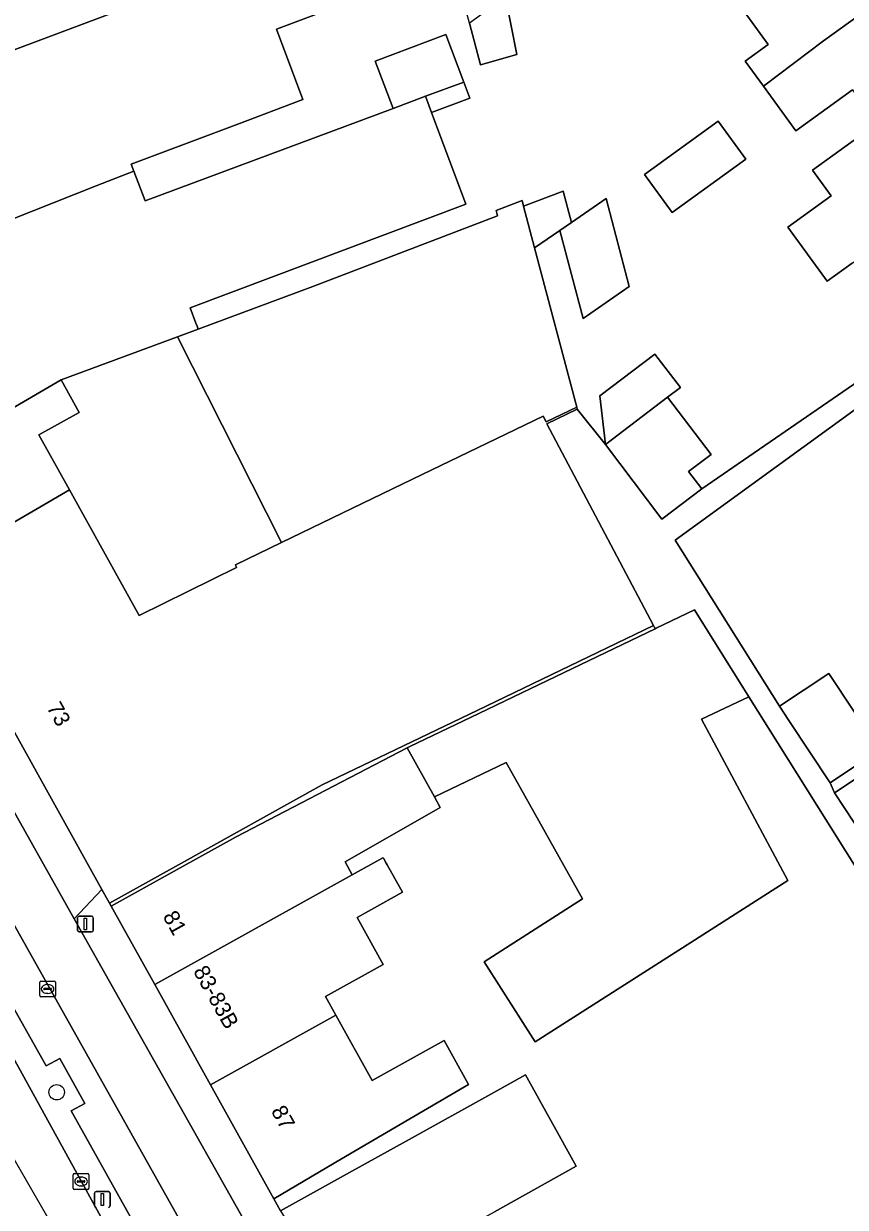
# Model space of a CAD drawing. Extents: x 161881 to 162523, y 381678 to 382381.
# Drawn here: x 162099.1 to 162151.2, y 381909.3 to 381984.4 of the extents above; entities that cross this region are included whole.
import ezdxf

# ---------------------------------------------------------------- set-up
doc = ezdxf.new("R2010")
doc.units = 0
for name, color, linetype in [('IMGEO_Berm_groen', 7, 'Continuous'), ('IMGEO_Boom', 7, 'Continuous'), ('IMGEO_Erf', 7, 'Continuous'), ('IMGEO_Fietspad_open', 7, 'Continuous'), ('IMGEO_Kolk', 7, 'Continuous'), ('IMGEO_Lichtmast', 7, 'Continuous'), ('IMGEO_Pand', 7, 'Continuous'), ('IMGEO_Pand_nummerreeks', 7, 'Continuous'), ('IMGEO_Parkeervlak_open', 7, 'Continuous'), ('IMGEO_Rijbaan_lokaal_gesloten', 7, 'Continuous'), ('IMGEO_Voetpad_open', 7, 'Continuous')]:
    doc.layers.add(name, color=color, linetype=linetype)

msp = doc.modelspace()

# ---------------------------------------------------------------- linework, layer by layer
at = {"layer": 'IMGEO_Berm_groen'}
msp.add_lwpolyline([(162071.636, 381967.886), (162076.565, 381958.577), (162107.811, 381901.826), (162108.729, 381902.414), (162110.128, 381903.311), (162108.772, 381905.652), (162107.884, 381905.166), (162102.118, 381915.454), (162102.985, 381915.921), (162101.417, 381918.762), (162100.535, 381918.293), (162094.757, 381928.54)], dxfattribs=at)
at = {"layer": 'IMGEO_Boom'}
msp.add_circle((162101.21, 381916.628), 0.489, dxfattribs=at)
at = {"layer": 'IMGEO_Erf'}
for points in [[(162088.878, 381991.295), (162094.493, 381981.199), (162124.179, 381992.364)], [(162125.323, 381987.847), (162115.138, 381984.016), (162116.818, 381979.55), (162112.686, 381977.996), (162105.938, 381975.458), (162106.111, 381975.02), (162106.819, 381973.14), (162122.531, 381978.989), (162121.401, 381981.991), (162125.885, 381983.677), (162127.02, 381980.66), (162127.406, 381979.635), (162124.971, 381978.729), (162127.156, 381972.918), (162109.673, 381966.342), (162110.039, 381965.369), (162110.109, 381965.182), (162110.177, 381965.001), (162117.448, 381967.695), (162129.146, 381972.188), (162129.064, 381972.524), (162130.709, 381973.143), (162130.801, 381972.795), (162133.313, 381973.74), (162133.841, 381971.754), (162136.036, 381973.274), (162137.511, 381967.703), (162134.579, 381965.674), (162133.103, 381971.247), (162131.502, 381970.146), (162134.174, 381960.054), (162134.209, 381959.922), (162135.993, 381957.684), (162135.646, 381960.777), (162139.13, 381963.42), (162140.746, 381961.291), (162139.941, 381960.68), (162142.691, 381957.057), (162141.26, 381955.971), (162142.099, 381954.866), (162155.378, 381964.012)], [(162151.659, 381980.171), (162148.072, 381977.568), (162146.018, 381980.399), (162144.863, 381981.99), (162146.312, 381983.042), (162143.669, 381986.685)], [(162151.63, 381969.178), (162150.052, 381968.034), (162147.56, 381971.47), (162150.299, 381973.457), (162149.133, 381975.065), (162153.215, 381978.026)], [(162161.41, 381966.864), (162140.416, 381951.63), (162147.039, 381941.108), (162150.163, 381943.18), (162153.377, 381938.326), (162150.238, 381936.248), (162150.507, 381935.6), (162155.548, 381938.937)], [(162158.021, 381921.094), (162145.094, 381941.696), (162142.094, 381940.269), (162147.556, 381930.049), (162140.649, 381925.635), (162131.552, 381919.822), (162128.311, 381924.893), (162134.552, 381928.882), (162129.711, 381937.528), (162125.164, 381935.343), (162125.512, 381934.681), (162119.488, 381931.238), (162119.947, 381930.412), (162121.875, 381931.484), (162121.933, 381931.457), (162122.106, 381931.146), (162122.158, 381931.053), (162123.131, 381929.304), (162121.17, 381928.214), (162120.249, 381927.702), (162121.906, 381924.722), (162118.249, 381922.689), (162118.9, 381921.518), (162121.208, 381917.368), (162125.767, 381919.903), (162127.316, 381917.118), (162119.275, 381912.403), (162114.979, 381909.883), (162115.406, 381909.104), (162119.776, 381911.535), (162123.36, 381913.529), (162128.916, 381916.62), (162130.922, 381917.736), (162134.148, 381911.935), (162128.959, 381909.049)]]:
    msp.add_lwpolyline(points, dxfattribs=at)
for points in [[(162126.111, 381989.03), (162128.955, 381989.793), (162129.671, 381986.056), (162130.37, 381982.407), (162128.086, 381981.748), (162127.369, 381984.391)], [(162138.482, 381974.79), (162143.141, 381978.171), (162144.891, 381975.762), (162140.231, 381972.381)], [(162108.867, 381964.516), (162101.493, 381961.784), (162102.644, 381959.714), (162100.084, 381958.29), (162102.018, 381954.814), (162106.444, 381946.857), (162112.612, 381949.9), (162112.537, 381950.052), (162115.472, 381951.478)], [(162139.141, 381946.01), (162139.038, 381946.204), (162127.861, 381940.832), (162118.036, 381936.109), (162108.932, 381931.046), (162104.562, 381928.615), (162104.671, 381928.417), (162109.041, 381930.848), (162112.594, 381932.824), (162123.423, 381938.453), (162123.598, 381938.538), (162127.969, 381940.639), (162131.792, 381942.477)]]:
    msp.add_lwpolyline(points, close=True, dxfattribs=at)
at = {"layer": 'IMGEO_Fietspad_open'}
for points in [[(162117.066, 381901.457), (162102.32, 381927.62), (162087.64, 381953.76), (162075.194, 381976.109)], [(162076.214, 381967.086), (162084.266, 381952.579), (162111.528, 381904.042)]]:
    msp.add_lwpolyline(points, dxfattribs=at)
at = {"layer": 'IMGEO_Kolk'}
for p, q in [((162100.134, 381922.752), (162100.134, 381923.604)), ((162100.209, 381923.678), (162101.061, 381923.678)), ((162100.393, 381923.172), (162100.393, 381923.184)), ((162100.831, 381923.135), (162100.433, 381923.135)), ((162100.436, 381923.221), (162100.834, 381923.221)), ((162100.622, 381923.458), (162100.647, 381923.458)), ((162100.877, 381923.184), (162100.877, 381923.172)), ((162101.135, 381923.604), (162101.135, 381922.752)), ((162101.061, 381922.678), (162100.209, 381922.678)), ((162100.645, 381922.898), (162100.62, 381922.898)), ((162102.256, 381910.547), (162102.256, 381911.399)), ((162102.331, 381911.473), (162103.183, 381911.473)), ((162102.744, 381911.253), (162102.769, 381911.253)), ((162103.257, 381911.399), (162103.257, 381910.547)), ((162103.183, 381910.473), (162102.331, 381910.473)), ((162102.515, 381910.967), (162102.515, 381910.979)), ((162102.953, 381910.93), (162102.555, 381910.93)), ((162102.558, 381911.016), (162102.956, 381911.016)), ((162102.767, 381910.693), (162102.742, 381910.693)), ((162102.999, 381910.979), (162102.999, 381910.967))]:
    msp.add_line(p, q, dxfattribs=at)
for points in [[(162100.134, 381922.752), (162100.134, 381923.604)], [(162100.209, 381923.678), (162101.061, 381923.678)], [(162101.135, 381923.604), (162101.135, 381922.752)], [(162101.061, 381922.678), (162100.209, 381922.678)], [(162102.256, 381910.547), (162102.256, 381911.399)], [(162102.331, 381911.473), (162103.183, 381911.473)], [(162103.257, 381911.399), (162103.257, 381910.547)], [(162103.183, 381910.473), (162102.331, 381910.473)]]:
    msp.add_lwpolyline(points, dxfattribs=at)
for centre, radius, start, end in [((162100.211, 381923.602), 0.0765, 91.55205, 178.44795), ((162100.211, 381923.602), 0.0765, 91.55205, 178.44795), ((162100.433, 381923.181), 0.0403, 85.87752, 175.75265), ((162100.43, 381923.171), 0.0366, 178.93798, 274.71019), ((162100.834, 381923.178), 0.043, 264.86636, 352.45326), ((162100.838, 381923.183), 0.0386, 1.73085, 96.63898), ((162101.059, 381923.602), 0.0765, 1.55205, 88.44795), ((162101.059, 381923.602), 0.0765, 1.55205, 88.44795), ((162100.211, 381922.754), 0.0765, 181.55205, 268.44795), ((162100.211, 381922.754), 0.0765, 181.55205, 268.44795), ((162101.059, 381922.754), 0.0765, 271.55205, 358.44795), ((162101.059, 381922.754), 0.0765, 271.55205, 358.44795), ((162102.333, 381911.397), 0.0765, 91.55205, 178.44795), ((162102.333, 381911.397), 0.0765, 91.55205, 178.44795), ((162103.181, 381911.397), 0.0765, 1.55205, 88.44795), ((162103.181, 381911.397), 0.0765, 1.55205, 88.44795), ((162102.333, 381910.549), 0.0765, 181.55205, 268.44795), ((162102.333, 381910.549), 0.0765, 181.55205, 268.44795), ((162102.555, 381910.976), 0.0403, 85.87752, 175.75265), ((162102.552, 381910.966), 0.0366, 178.93798, 274.71019), ((162102.956, 381910.973), 0.043, 264.86636, 352.45326), ((162102.96, 381910.978), 0.0386, 1.73085, 96.63898), ((162103.181, 381910.549), 0.0765, 271.55205, 358.44795), ((162103.181, 381910.549), 0.0765, 271.55205, 358.44795)]:
    msp.add_arc(centre, radius, start, end, dxfattribs=at)
for centre, major_axis, ratio, start_param, end_param in [((162100.621, 381923.178), (-0.387, 0.002), 0.722429, 4.712389, 7.853982), ((162100.646, 381923.178), (-0.39, 0.002), 0.717154, 1.570796, 4.712389), ((162102.743, 381910.973), (-0.387, 0.002), 0.722429, 4.712389, 7.853982), ((162102.768, 381910.973), (-0.39, 0.002), 0.717154, 1.570796, 4.712389)]:
    msp.add_ellipse(centre, major_axis=major_axis, ratio=ratio, start_param=start_param, end_param=end_param, dxfattribs=at)
at = {"layer": 'IMGEO_Lichtmast'}
for p, q in [((162102.534, 381926.889), (162102.534, 381927.689)), ((162102.534, 381927.689), (162102.534, 381926.889)), ((162102.634, 381927.789), (162103.424, 381927.789)), ((162103.424, 381927.789), (162102.634, 381927.789)), ((162103.524, 381927.689), (162103.524, 381926.889)), ((162103.524, 381926.889), (162103.524, 381927.689)), ((162103.424, 381926.789), (162102.634, 381926.789)), ((162102.634, 381926.789), (162103.424, 381926.789)), ((162103.603, 381909.434), (162103.603, 381910.234)), ((162103.603, 381910.234), (162103.603, 381909.434)), ((162103.703, 381910.334), (162104.493, 381910.334)), ((162104.493, 381910.334), (162103.703, 381910.334)), ((162104.593, 381910.234), (162104.593, 381909.434)), ((162104.593, 381909.434), (162104.593, 381910.234))]:
    msp.add_line(p, q, dxfattribs=at)
for points in [[(162102.954, 381927.664), (162103.104, 381927.664), (162103.104, 381926.914), (162102.954, 381926.914), (162102.954, 381927.664)], [(162104.023, 381910.209), (162104.173, 381910.209), (162104.173, 381909.459), (162104.023, 381909.459), (162104.023, 381910.209)]]:
    msp.add_lwpolyline(points, dxfattribs=at)
for centre, start, end in [((162102.634, 381927.689), 90, 180), ((162102.634, 381927.689), 90, 180), ((162103.424, 381927.689), 0, 90), ((162103.424, 381927.689), 360, 90), ((162102.634, 381926.889), 180, 270), ((162102.634, 381926.889), 180, 270), ((162103.424, 381926.889), 270, 0), ((162103.424, 381926.889), 270, 0), ((162103.703, 381910.234), 90, 180), ((162103.703, 381910.234), 90, 180), ((162104.493, 381910.234), 0, 90), ((162104.493, 381910.234), 360, 90), ((162103.703, 381909.434), 180, 270), ((162103.703, 381909.434), 180, 270), ((162104.493, 381909.434), 270, 0), ((162104.493, 381909.434), 270, 0)]:
    msp.add_arc(centre, 0.1, start, end, dxfattribs=at)
at = {"layer": 'IMGEO_Pand'}
for points in [[(162112.686, 381977.996), (162116.818, 381979.55), (162115.138, 381984.016), (162125.323, 381987.847), (162124.179, 381992.364), (162094.493, 381981.199), (162078.888, 381975.33), (162080.448, 381972.475), (162080.234, 381972.356), (162084.224, 381965.182), (162091.602, 381969.28), (162103.707, 381974.071), (162106.111, 381975.02), (162105.938, 381975.458)], [(162155.55, 381987.421), (162151.802, 381992.587), (162147.756, 381989.651), (162143.669, 381986.685), (162146.312, 381983.042), (162144.863, 381981.99), (162146.018, 381980.399), (162149.823, 381983.266)], [(162155.55, 381987.421), (162149.823, 381983.266), (162146.018, 381980.399), (162148.072, 381977.568), (162151.659, 381980.171), (162153.215, 381978.026), (162153.482, 381978.221), (162159.209, 381982.377)], [(162129.671, 381986.056), (162127.369, 381984.391), (162128.086, 381981.748), (162130.37, 381982.407)], [(162122.531, 381978.989), (162124.585, 381979.754), (162127.02, 381980.66), (162125.885, 381983.677), (162121.401, 381981.991)], [(162162.869, 381977.333), (162159.209, 381982.377), (162153.482, 381978.221), (162153.215, 381978.026), (162149.133, 381975.065), (162150.299, 381973.457), (162147.56, 381971.47), (162150.052, 381968.034), (162151.63, 381969.178), (162155.012, 381971.631), (162153.609, 381973.567), (162155.47, 381974.917), (162156.874, 381972.982)], [(162127.406, 381979.635), (162127.02, 381980.66), (162124.585, 381979.754), (162124.971, 381978.729)], [(162127.156, 381972.918), (162124.971, 381978.729), (162124.585, 381979.754), (162122.531, 381978.989), (162106.819, 381973.14), (162106.111, 381975.02), (162103.707, 381974.071), (162091.602, 381969.28), (162084.224, 381965.182), (162089.877, 381955.018), (162092.037, 381956.277), (162101.493, 381961.784), (162108.867, 381964.516), (162110.177, 381965.001), (162110.109, 381965.182), (162110.039, 381965.369), (162109.673, 381966.342)], [(162138.482, 381974.79), (162140.231, 381972.381), (162144.891, 381975.762), (162143.141, 381978.171)], [(162130.801, 381972.795), (162131.502, 381970.146), (162133.103, 381971.247), (162133.841, 381971.754), (162133.313, 381973.74)], [(162131.502, 381970.146), (162130.801, 381972.795), (162130.709, 381973.143), (162129.064, 381972.524), (162129.146, 381972.188), (162117.448, 381967.695), (162110.177, 381965.001), (162108.867, 381964.516), (162115.472, 381951.478), (162123.76, 381955.478), (162132.047, 381959.477), (162132.237, 381959.113), (162134.174, 381960.054)], [(162133.841, 381971.754), (162133.103, 381971.247), (162134.579, 381965.674), (162137.511, 381967.703), (162136.036, 381973.274)], [(162139.941, 381960.68), (162140.746, 381961.291), (162139.13, 381963.42), (162135.646, 381960.777), (162135.993, 381957.684)], [(162101.493, 381961.784), (162092.037, 381956.277), (162095.093, 381950.781), (162102.018, 381954.814), (162100.084, 381958.29), (162102.644, 381959.714)], [(162142.691, 381957.057), (162139.941, 381960.68), (162135.993, 381957.684), (162139.581, 381952.956), (162142.099, 381954.866), (162141.26, 381955.971)], [(162102.018, 381954.814), (162095.093, 381950.781), (162092.037, 381956.277), (162089.877, 381955.018), (162090.11, 381954.599), (162104.077, 381929.487), (162104.562, 381928.615), (162108.932, 381931.046), (162118.036, 381936.109), (162127.861, 381940.832), (162139.038, 381946.204), (162132.287, 381958.988), (162134.209, 381959.922), (162134.174, 381960.054), (162132.237, 381959.113), (162132.047, 381959.477), (162123.76, 381955.478), (162115.472, 381951.478), (162112.537, 381950.052), (162112.612, 381949.9), (162106.444, 381946.857)], [(162142.094, 381940.269), (162145.094, 381941.696), (162141.641, 381947.199), (162139.216, 381946.046), (162139.141, 381946.01), (162131.792, 381942.477), (162127.969, 381940.639), (162123.598, 381938.538), (162123.423, 381938.453), (162125.164, 381935.343), (162129.711, 381937.528), (162134.552, 381928.882), (162128.311, 381924.893), (162131.552, 381919.822), (162140.649, 381925.635), (162147.556, 381930.049)], [(162150.163, 381943.18), (162147.039, 381941.108), (162147.026, 381941.1), (162147.624, 381940.198), (162150.238, 381936.248), (162153.377, 381938.326)], [(162158, 381935.233), (162155.548, 381938.937), (162150.507, 381935.6), (162152.959, 381931.896)], [(162119.947, 381930.412), (162119.488, 381931.238), (162125.512, 381934.681), (162125.164, 381935.343), (162123.423, 381938.453), (162112.594, 381932.824), (162109.041, 381930.848), (162104.671, 381928.417), (162107.432, 381923.452)], [(162121.906, 381924.722), (162120.249, 381927.702), (162121.17, 381928.214), (162123.131, 381929.304), (162122.158, 381931.053), (162122.106, 381931.146), (162121.933, 381931.457), (162121.875, 381931.484), (162119.947, 381930.412), (162107.432, 381923.452), (162110.963, 381917.104), (162118.9, 381921.518), (162118.249, 381922.689)], [(162110.963, 381917.104), (162114.979, 381909.883), (162119.275, 381912.403), (162127.316, 381917.118), (162125.767, 381919.903), (162121.208, 381917.368), (162118.9, 381921.518)], [(162123.36, 381913.529), (162119.776, 381911.535), (162115.406, 381909.104), (162118.876, 381903.441), (162123.246, 381905.872), (162126.727, 381907.808), (162127.469, 381908.221), (162128.959, 381909.049), (162134.148, 381911.935), (162130.922, 381917.736), (162128.916, 381916.62)]]:
    msp.add_lwpolyline(points, close=True, dxfattribs=at)
at = {"layer": 'IMGEO_Parkeervlak_open'}
msp.add_lwpolyline([(162075.702, 381965.694), (162075.168, 381963.546), (162078.528, 381957.526), (162079.42, 381958.024), (162080.998, 381955.203), (162080.108, 381954.721), (162085.861, 381944.447), (162086.738, 381944.939), (162088.219, 381942.206), (162087.448, 381941.624), (162093.19, 381931.352), (162094.05, 381931.846), (162095.649, 381929.029), (162094.757, 381928.54), (162100.535, 381918.293), (162101.417, 381918.762), (162102.985, 381915.921), (162102.118, 381915.454), (162107.884, 381905.166), (162108.772, 381905.652), (162110.128, 381903.311), (162111.528, 381904.042), (162084.266, 381952.579), (162076.214, 381967.086)], dxfattribs=at)
at = {"layer": 'IMGEO_Rijbaan_lokaal_gesloten'}
for points in [[(161957.883, 382126.571), (162018.616, 382046.024), (162020.205, 382044.026), (162035.676, 382024.566), (162039.393, 382017.803), (162056.257, 381987.116), (162074.133, 381954.589), (162112.413, 381888.285), (162135.308, 381862.267), (162145.259, 381854.842)], [(162120.092, 381883.14), (162118.816, 381884.72), (162116.672, 381887.684), (162107.811, 381901.826), (162076.565, 381958.577), (162071.636, 381967.886), (162066.835, 381976.766), (162066.256, 381977.793), (162065.992, 381978.592), (162065.582, 381979.503), (162062.076, 381986.301), (162058.206, 381993.875), (162057.987, 381994.304)]]:
    msp.add_lwpolyline(points, dxfattribs=at)
at = {"layer": 'IMGEO_Voetpad_open'}
for points in [[(162161.41, 381966.864), (162163.309, 381968.242), (162167.356, 381971.177), (162166.617, 381972.166), (162160.622, 381967.816), (162155.378, 381964.012), (162142.099, 381954.866), (162139.581, 381952.956), (162135.993, 381957.684), (162134.209, 381959.922), (162132.287, 381958.988), (162139.038, 381946.204), (162139.141, 381946.01), (162139.216, 381946.046), (162141.641, 381947.199), (162145.094, 381941.696), (162158.021, 381921.094)], [(162152.959, 381931.896), (162150.507, 381935.6), (162150.238, 381936.248), (162147.624, 381940.198), (162147.026, 381941.1), (162147.039, 381941.108), (162140.416, 381951.63), (162161.41, 381966.864)], [(162115.406, 381909.104), (162114.979, 381909.883), (162110.963, 381917.104), (162107.432, 381923.452), (162104.671, 381928.417), (162104.562, 381928.615), (162104.077, 381929.487), (162102.32, 381927.62), (162117.066, 381901.457)]]:
    msp.add_lwpolyline(points, dxfattribs=at)
msp.add_lwpolyline([(162090.11, 381954.599), (162087.64, 381953.76), (162102.32, 381927.62), (162104.077, 381929.487)], close=True, dxfattribs=at)

# ---------------------------------------------------------------- texts
at = {"layer": 'IMGEO_Pand_nummerreeks'}
for s, rotation, p in [('73', 299.08207, (162100.548, 381941.017)), ('81', 299.0774, (162107.907, 381927.782)), ('83-83B', 299.08313, (162109.841, 381924.306)), ('87', 299.08087, (162114.771, 381915.441))]:
    msp.add_text(s, height=1, rotation=rotation, dxfattribs=at).set_placement(p)

doc.saveas('drawing.dxf')
